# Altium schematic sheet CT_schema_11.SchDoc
size 385 x 278 mm
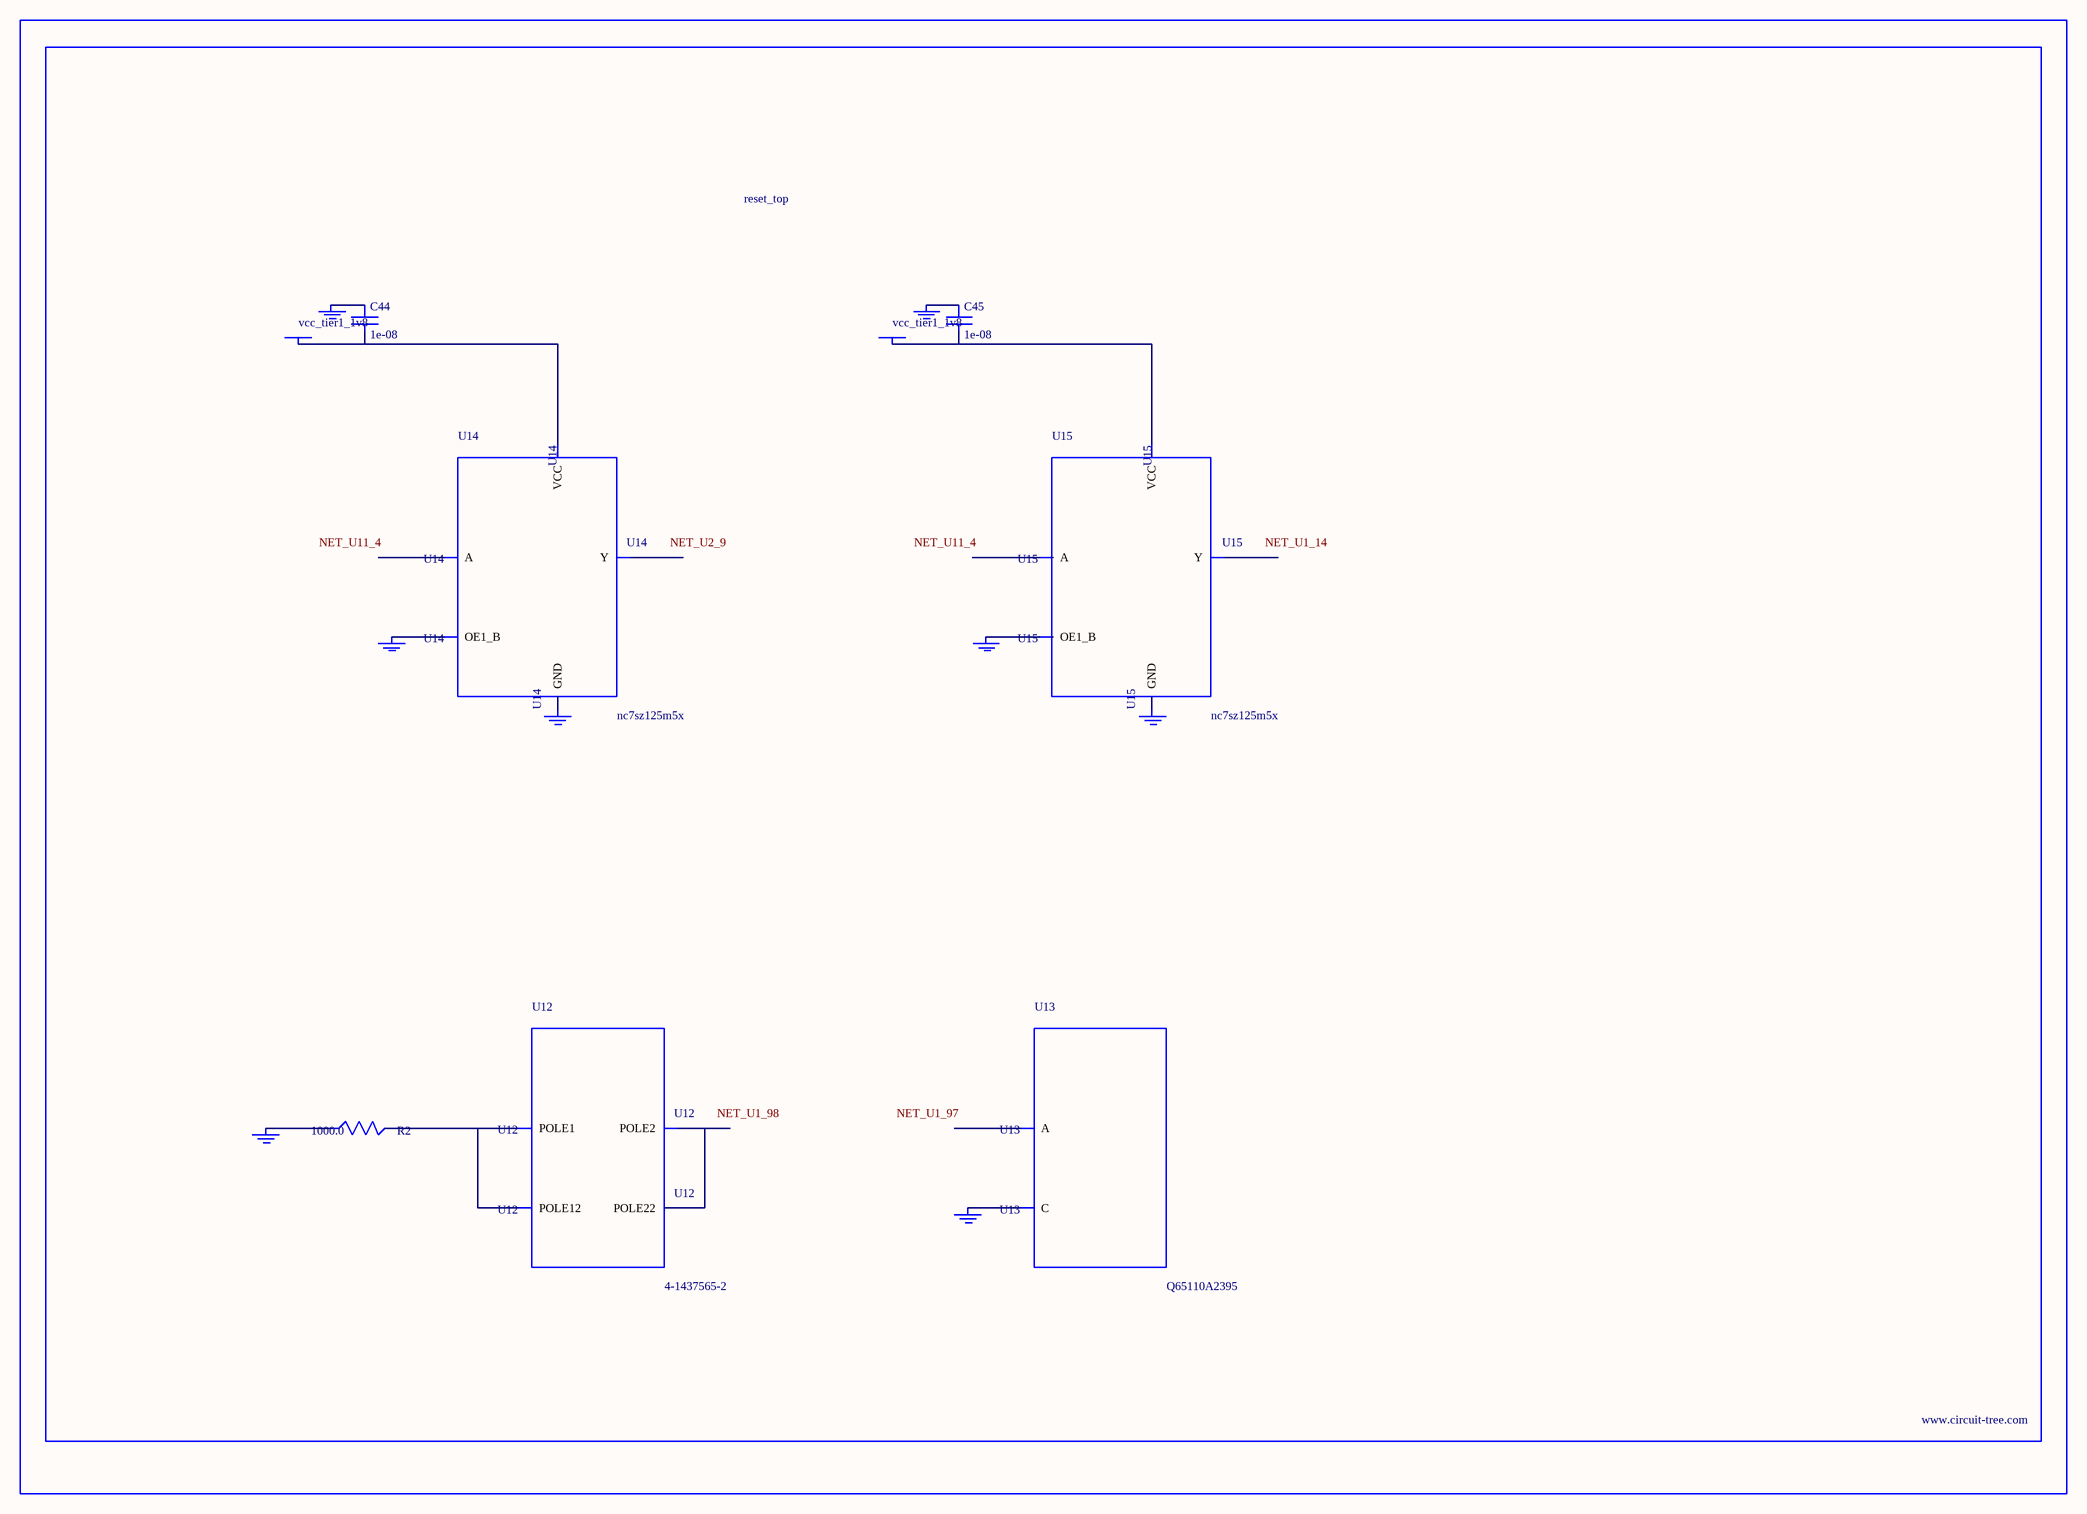
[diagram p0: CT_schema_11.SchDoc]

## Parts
BORDER10  (no value)
C44  1e-08  [C0402]
C45  1e-08  [C0402]
GND_INSTANCE_10_0  (no value)
GND_INSTANCE_10_1  (no value)
GND_INSTANCE_10_2  (no value)
GND_INSTANCE_10_3  (no value)
GND_INSTANCE_10_4  (no value)
GND_INSTANCE_10_5  (no value)
GND_INSTANCE_10_6  (no value)
GND_INSTANCE_10_7  (no value)
POWER_INSTANCE_10_0  vcc_tier1_1v8
POWER_INSTANCE_10_1  vcc_tier1_1v8
R2  1000.0  [R0603]
U12  4-1437565-2  [SW_4-1437565-2]
U13  Q65110A2395  [LGM67K-G1J2-24-Z]
U14  nc7sz125m5x  [NC7SZ125M5X]
U15  nc7sz125m5x  [NC7SZ125M5X]

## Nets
NetC44_1: C44.1 GND_INSTANCE_10_2.0(GND)
NetC44_2: C44.2 POWER_INSTANCE_10_0.0(PWR) U14.5(VCC)
NetC45_1: C45.1 GND_INSTANCE_10_5.0(GND)
NetC45_2: C45.2 POWER_INSTANCE_10_1.0(PWR) U15.5(VCC)
NetGND_INSTANCE_10_0_0: GND_INSTANCE_10_0.0(GND) R2.1
NetGND_INSTANCE_10_1_0: GND_INSTANCE_10_1.0(GND) U13.C
NetGND_INSTANCE_10_3_0: GND_INSTANCE_10_3.0(GND) U14.1(OE1_B)
NetGND_INSTANCE_10_4_0: GND_INSTANCE_10_4.0(GND) U14.3(GND)
NetGND_INSTANCE_10_6_0: GND_INSTANCE_10_6.0(GND) U15.1(OE1_B)
NetGND_INSTANCE_10_7_0: GND_INSTANCE_10_7.0(GND) U15.3(GND)
NetR2_2: R2.2 U12.1(POLE1) U12.2(POLE12)
NetU12_3: U12.3(POLE2) U12.4(POLE22)

Not connected (* = marked no-connect by the designer): U13 A; U14 2(A) 4(Y); U15 2(A) 4(Y)

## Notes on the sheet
- Labels drawn without touching a wire or pin: NET_U1_14, NET_U1_97, NET_U1_98, NET_U2_9, NET_U11_4

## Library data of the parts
BORDER10 = BORDER_PAGE10
C44 C45 = C0402C103K3RAC
GND_INSTANCE_10_0-GND_INSTANCE_10_7 = GND
POWER_INSTANCE_10_0 POWER_INSTANCE_10_1 = PWR
R2 = RC0603JR-071KL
